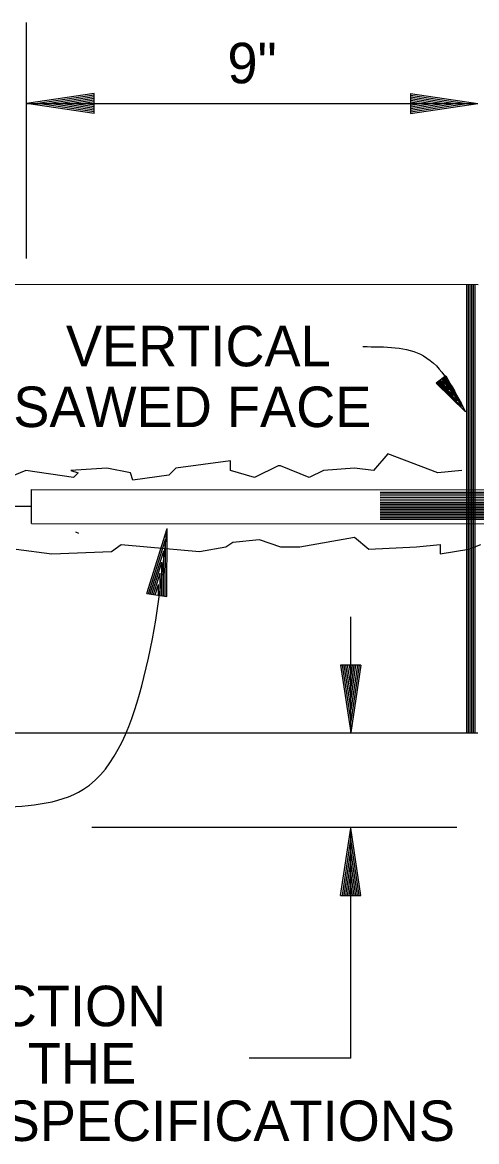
# Model space of a CAD drawing. Extents: x 1375738 to 1375905, y 380661 to 380875.
# Drawn here: x 1375751.44 to 1375756.82, y 380836.45 to 380849.71 of the extents above; entities that cross this region are included whole.
import ezdxf

# ---------------------------------------------------------------- set-up
doc = ezdxf.new("R2010")
doc.units = 0
doc.layers.add('R_Draft', color=7, linetype='Continuous')

msp = doc.modelspace()

# ---------------------------------------------------------------- linework, layer by layer
at = {"layer": 'R_Draft'}
for p, q in [((1375751.49, 380846.912), (1375751.49, 380849.708)), ((1375752.29, 380848.867), (1375751.49, 380848.747)), ((1375752.29, 380848.847), (1375751.623, 380848.747)), ((1375752.29, 380848.827), (1375751.761, 380848.747)), ((1375752.29, 380848.807), (1375751.894, 380848.747)), ((1375752.29, 380848.786), (1375752.03, 380848.747)), ((1375752.29, 380848.766), (1375752.163, 380848.747)), ((1375752.29, 380848.627), (1375752.29, 380848.867)), ((1375756.039, 380848.867), (1375756.839, 380848.747)), ((1375756.039, 380848.867), (1375756.039, 380848.627)), ((1375756.039, 380848.847), (1375756.706, 380848.747)), ((1375756.039, 380848.827), (1375756.568, 380848.747)), ((1375756.039, 380848.807), (1375756.435, 380848.747)), ((1375756.039, 380848.786), (1375756.299, 380848.747)), ((1375756.039, 380848.766), (1375756.166, 380848.747)), ((1375751.49, 380848.747), (1375756.839, 380848.747)), ((1375752.29, 380848.627), (1375751.49, 380848.747)), ((1375752.29, 380848.647), (1375751.623, 380848.747)), ((1375752.29, 380848.668), (1375751.761, 380848.747)), ((1375752.29, 380848.688), (1375751.894, 380848.747)), ((1375752.29, 380848.708), (1375752.03, 380848.747)), ((1375752.29, 380848.728), (1375752.163, 380848.747)), ((1375756.039, 380848.627), (1375756.839, 380848.747)), ((1375756.039, 380848.708), (1375756.299, 380848.747)), ((1375756.039, 380848.668), (1375756.568, 380848.747)), ((1375756.039, 380848.647), (1375756.706, 380848.747)), ((1375756.039, 380848.688), (1375756.435, 380848.747)), ((1375756.039, 380848.728), (1375756.166, 380848.747)), ((1375747.225, 380846.607), (1375756.842, 380846.602)), ((1375756.708, 380841.288), (1375756.708, 380846.602)), ((1375756.728, 380841.288), (1375756.728, 380846.602)), ((1375756.748, 380841.288), (1375756.748, 380846.602)), ((1375756.768, 380841.288), (1375756.768, 380846.602)), ((1375756.788, 380841.288), (1375756.788, 380846.602)), ((1375756.808, 380841.288), (1375756.808, 380846.602)), ((1375756.46, 380845.521), (1375756.345, 380845.434)), ((1375756.364, 380845.449), (1375756.593, 380845.224)), ((1375756.374, 380845.456), (1375756.545, 380845.288)), ((1375756.384, 380845.464), (1375756.496, 380845.353)), ((1375756.393, 380845.471), (1375756.448, 380845.417)), ((1375756.412, 380845.484), (1375756.448, 380845.417)), ((1375756.421, 380845.492), (1375756.496, 380845.353)), ((1375756.431, 380845.499), (1375756.545, 380845.288)), ((1375756.441, 380845.506), (1375756.593, 380845.224)), ((1375756.451, 380845.514), (1375756.643, 380845.158)), ((1375756.46, 380845.521), (1375756.691, 380845.094)), ((1375756.345, 380845.434), (1375756.691, 380845.094)), ((1375756.355, 380845.442), (1375756.643, 380845.158)), ((1375751.547, 380843.771), (1375751.547, 380844.172)), ((1375751.548, 380844.172), (1375762.629, 380844.166)), ((1375755.679, 380844.141), (1375762.36, 380844.137)), ((1375755.679, 380844.121), (1375762.36, 380844.117)), ((1375755.679, 380844.101), (1375762.36, 380844.097)), ((1375755.679, 380844.081), (1375762.36, 380844.077)), ((1375755.679, 380844.061), (1375762.36, 380844.057)), ((1375755.679, 380844.041), (1375762.36, 380844.037)), ((1375755.679, 380844.021), (1375762.36, 380844.017)), ((1375755.679, 380844.001), (1375762.36, 380843.997)), ((1375751.547, 380843.972), (1375748.317, 380843.972)), ((1375755.679, 380843.981), (1375762.36, 380843.977)), ((1375755.679, 380843.961), (1375762.36, 380843.957)), ((1375755.679, 380843.941), (1375762.36, 380843.937)), ((1375755.679, 380843.921), (1375762.36, 380843.917)), ((1375755.679, 380843.901), (1375762.36, 380843.897)), ((1375755.679, 380843.881), (1375762.36, 380843.877)), ((1375755.679, 380843.861), (1375762.36, 380843.857)), ((1375751.547, 380843.771), (1375762.629, 380843.765)), ((1375755.679, 380843.841), (1375762.36, 380843.837)), ((1375755.679, 380843.821), (1375762.36, 380843.817)), ((1375752.915, 380842.941), (1375753.157, 380843.713)), ((1375753.152, 380842.904), (1375753.157, 380843.713)), ((1375752.934, 380842.938), (1375753.136, 380843.581)), ((1375753.132, 380842.907), (1375753.136, 380843.581)), ((1375752.955, 380842.935), (1375753.115, 380843.445)), ((1375753.112, 380842.91), (1375753.115, 380843.445)), ((1375752.974, 380842.932), (1375753.094, 380843.314)), ((1375753.092, 380842.914), (1375753.094, 380843.314)), ((1375752.995, 380842.929), (1375753.073, 380843.18)), ((1375753.072, 380842.917), (1375753.073, 380843.18)), ((1375752.915, 380842.941), (1375753.152, 380842.904)), ((1375753.015, 380842.926), (1375753.053, 380843.048)), ((1375753.052, 380842.92), (1375753.053, 380843.048)), ((1375755.331, 380841.292), (1375755.331, 380842.666)), ((1375755.211, 380842.092), (1375755.331, 380841.292)), ((1375755.451, 380842.092), (1375755.211, 380842.092)), ((1375755.231, 380842.092), (1375755.331, 380841.426)), ((1375755.251, 380842.092), (1375755.331, 380841.563)), ((1375755.271, 380842.092), (1375755.331, 380841.696)), ((1375755.291, 380842.092), (1375755.331, 380841.832)), ((1375755.312, 380842.092), (1375755.331, 380841.966)), ((1375755.451, 380842.092), (1375755.331, 380841.292)), ((1375755.369, 380842.092), (1375755.331, 380841.832)), ((1375755.41, 380842.092), (1375755.331, 380841.563)), ((1375755.431, 380842.092), (1375755.331, 380841.426)), ((1375755.39, 380842.092), (1375755.331, 380841.696)), ((1375755.349, 380842.092), (1375755.331, 380841.966)), ((1375747.222, 380841.294), (1375756.839, 380841.288)), ((1375756.591, 380840.169), (1375752.262, 380840.169)), ((1375755.212, 380839.362), (1375755.331, 380840.162)), ((1375755.332, 380837.436), (1375755.331, 380840.162)), ((1375755.452, 380839.362), (1375755.331, 380840.162)), ((1375755.232, 380839.362), (1375755.331, 380840.029)), ((1375755.432, 380839.362), (1375755.331, 380840.029)), ((1375755.252, 380839.362), (1375755.331, 380839.891)), ((1375755.411, 380839.362), (1375755.331, 380839.891)), ((1375755.272, 380839.362), (1375755.331, 380839.758)), ((1375755.391, 380839.362), (1375755.331, 380839.758)), ((1375755.293, 380839.362), (1375755.331, 380839.622)), ((1375755.371, 380839.362), (1375755.331, 380839.622)), ((1375755.313, 380839.362), (1375755.331, 380839.489)), ((1375755.351, 380839.362), (1375755.331, 380839.489)), ((1375755.212, 380839.362), (1375755.452, 380839.362)), ((1375755.332, 380837.436), (1375754.128, 380837.436))]:
    msp.add_line(p, q, dxfattribs=at)
for points in [[(1375756.647, 380844.398), (1375756.365, 380844.37), (1375755.772, 380844.596), (1375755.602, 380844.398), (1375755.376, 380844.426), (1375755.009, 380844.398), (1375754.84, 380844.314), (1375754.501, 380844.455), (1375754.473, 380844.455), (1375754.19, 380844.314), (1375753.908, 380844.398), (1375753.908, 380844.511), (1375753.258, 380844.426), (1375753.174, 380844.342), (1375752.75, 380844.285), (1375752.722, 380844.37), (1375752.439, 380844.426), (1375752.016, 380844.398), (1375752.101, 380844.37), (1375752.044, 380844.314), (1375751.479, 380844.398), (1375750.999, 380844.201)], [(1375751.366, 380843.466), (1375751.79, 380843.41), (1375752.496, 380843.438), (1375752.609, 380843.523), (1375752.919, 380843.495), (1375753.541, 380843.438), (1375753.851, 380843.495), (1375753.936, 380843.551), (1375754.247, 380843.579), (1375754.501, 380843.495), (1375754.727, 380843.495), (1375755.376, 380843.608), (1375755.546, 380843.466), (1375756.111, 380843.495), (1375756.393, 380843.523), (1375756.393, 380843.41), (1375756.732, 380843.466), (1375756.873, 380843.523)], [(1375752.068, 380843.67), (1375752.105, 380843.656)]]:
    msp.add_lwpolyline(points, dxfattribs=at)
for points in [[(1375755.476, 380845.866), (1375756.194, 380845.756), (1375756.691, 380845.094)], [(1375751.059, 380840.4), (1375752.163, 380840.621), (1375752.881, 380841.946), (1375753.157, 380843.713)]]:
    msp.add_spline(points, degree=3, dxfattribs=at)

# ---------------------------------------------------------------- texts
for s, p in [('9"', (1375753.87, 380848.987)), ('VERTICAL', (1375751.956, 380845.633)), ('SAWED FACE', (1375751.332, 380844.913)), ('SEE SUBSECTION', (1375747.509, 380837.813)), ('507.05(b) OF THE', (1375747.509, 380837.133)), ('STANDARD SPECIFICATIONS', (1375747.509, 380836.453))]:
    msp.add_text(s, height=0.48, dxfattribs=at).set_placement(p)

doc.saveas('drawing.dxf')
